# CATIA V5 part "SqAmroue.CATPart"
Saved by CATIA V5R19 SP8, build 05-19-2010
Part number: SqAmroue
Publications: "Plan.1", "Point.1"
Bounding box of the stored display mesh (mm): x 0 to 0, y 0 to 250, z 0 to 0
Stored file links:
  F:\Travail\2e année\IAO\Projetsave\SqAmroue.CATPart
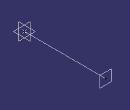
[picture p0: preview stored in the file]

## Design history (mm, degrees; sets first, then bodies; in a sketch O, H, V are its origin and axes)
Set1
  Point1: (0, 0, 0)
  Plane1: type Offset, RefPlane zx-plane, Offset 250
  Line1: type Normal, RefPoint Point1, RefSkin zx-plane, Start 0, End 250
Body1 (main body)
